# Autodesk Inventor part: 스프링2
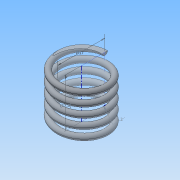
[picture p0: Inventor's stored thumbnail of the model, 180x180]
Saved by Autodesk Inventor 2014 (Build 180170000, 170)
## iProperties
Created: 2016-03
Part Number: 스프링2
Material: 일반
Document SubType Name: Modeling
Designer: net
Density: 1 g/cm^3
Appearance: 기본값
Author: net
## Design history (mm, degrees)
sketch "스케치1"
  geometry: L1 (0, 0)-(8.5, 0); L2 (8.5, 0)-(8.5, 17.5); L3 (8.5, 17.5)-(0, 17.5); L4 (0, 17.5)-(0, 0); C1 r 1 at (8.5, 0)
  constraints: 8 end point, 2 parallel, 1 centre point, 1 coincident, 1 horizontal, 1 perpendicular
  dimensions: "d0" = 17.5 distance of L3.end L1.start (derived); "d1" = 2 diameter of C1; "d2" = 17 diameter of L2 L4
feature "코일1" sketch "스케치1" pitch "d3" = 10; turns "d5" = 5; dims "d4" = 17.5 (= d0), "d6" = 0, angle "d7" = 90 deg, angle "d8" = 90 deg, "d9" = 0, "d10" = 0
sketch "스케치2"
  geometry: L1 (0, 7.5)-(0, 9.5) reference; 1 further point
  constraints: 1 vertical alignment
extrude "돌출1" cut sketch "스케치2" stored distance "d11" = 10; taper "d12" = 0 deg
node "작업 평면1"
sketch "스케치3"
  geometry: L1 (0, -2)-(0, 0) reference; 1 further point
  constraints: 1 vertical alignment
extrude "돌출2" cut sketch "스케치3" stored distance "d13" = 10; taper "d14" = 0 deg
node "솔리드1"
node "절단 모서리 투영1"
node "절단 모서리 투영2"
